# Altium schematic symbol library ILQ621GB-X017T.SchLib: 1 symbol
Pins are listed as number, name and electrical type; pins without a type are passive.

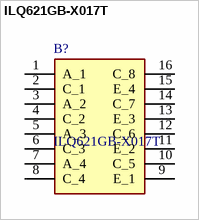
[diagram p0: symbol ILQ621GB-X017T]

## ILQ621GB-X017T
designator B?
Transistor Output Optocouplers Phototransistor Out Quad CTR > 100%; Manufacturer_Name: Vishay; Geometry.Height: 4.7mm
footprint SOP254P1030X470-16N
pins: 1 A_1, 2 C_1, 3 A_2, 4 C_2, 5 A_3, 6 C_3, 7 A_4, 8 C_4, 9 E_1, 10 C_5, 11 E_2, 12 C_6, 13 E_3, 14 C_7, 15 E_4, 16 C_8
